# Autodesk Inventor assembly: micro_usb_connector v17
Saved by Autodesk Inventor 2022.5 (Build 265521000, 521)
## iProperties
Created: 2024-12
Part Number: micro_usb_connector v17
Document SubType Name: Assembly
Designer: AdminForWorker
Title: micro_usb_connector v17
Author: AdminForWorker
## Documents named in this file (5)
- c:\worker\convert-fusion-r05-cosv3\tmp\job-1\35\temp\files\545dca92-a972-481a-9197-dd1a1176500e\micro_usb_connector v17.iam
- c:\worker\convert-fusion-r05-cosv3\tmp\job-1\35\temp\files\545dca92-a972-481a-9197-dd1a1176500e\shield.ipt
- c:\worker\convert-fusion-r05-cosv3\tmp\job-1\35\temp\files\545dca92-a972-481a-9197-dd1a1176500e\socket_housing.ipt
- c:\worker\convert-fusion-r05-cosv3\tmp\job-1\35\temp\files\545dca92-a972-481a-9197-dd1a1176500e\socket_plate.ipt
- c:\worker\convert-fusion-r05-cosv3\tmp\job-1\35\temp\files\545dca92-a972-481a-9197-dd1a1176500e\terminal.ipt
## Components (8 placed, 4 different names)
1. shield:1
2. socket_housing:1
3. socket_plate:1
4. terminal:1
5. terminal:2
6. terminal:3
7. terminal:4
8. terminal:5
